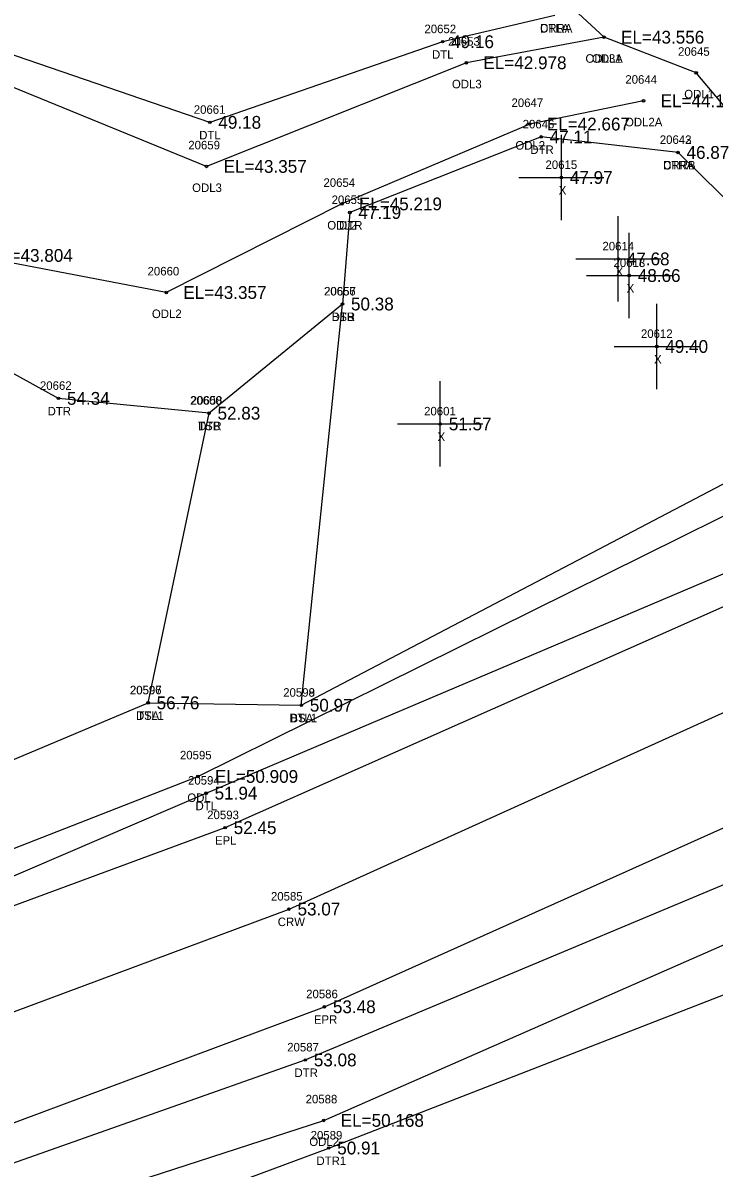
# Model space of a CAD drawing. Extents: x 2420351 to 2422725, y 845330 to 846558.
# Drawn here: x 2421635.3 to 2421716.5, y 845732.5 to 845866.8 of the extents above; entities that cross this region are included whole.
import ezdxf

# ---------------------------------------------------------------- set-up
doc = ezdxf.new("R2010")
doc.units = 0
for name, color, linetype in [('RD_DTM_BkLn1', 7, 'Continuous'), ('RD_DTM_BkLn2', 7, 'Continuous'), ('RD_DTM_BkLn_txCode', 7, 'Continuous'), ('RD_EX_H2O', 7, 'Continuous'), ('RD_EX_H2O_txCode', 7, 'Continuous'), ('RD_EX_Misc', 7, 'Continuous'), ('RD_EX_Misc_txCode', 7, 'Continuous'), ('RD_EX_Road', 7, 'Continuous'), ('RD_EX_Road_txCode', 7, 'Continuous'), ('RD_EX_TX_H2O_ELEV', 7, 'Continuous'), ('RD_EX_TX_Misc_ELEV', 7, 'Continuous'), ('RD_EX_TX_Road_ELEV', 7, 'Continuous'), ('RD_HC_Survey_ELEV', 7, 'Continuous'), ('RD_HC_Survey_txCode', 7, 'Continuous'), ('RD_SMD_Locator', 7, 'Continuous')]:
    doc.layers.add(name, color=color, linetype=linetype)

msp = doc.modelspace()

# ---------------------------------------------------------------- linework, layer by layer
at = {"layer": 'RD_DTM_BkLn1'}
msp.add_lwpolyline([(2420378.71, 845690.53), (2420439.5, 845704.09), (2420489.95, 845712.49), (2420551.89, 845719.42), (2420551.95, 845719.57), (2420607.12, 845722.67), (2420682.92, 845723.04), (2420749.65, 845719.68), (2420796.31, 845715.7), (2420900.74, 845705.33), (2421018.16, 845694.11), (2421114.61, 845684.8), (2421175.74, 845680.1), (2421234.97, 845678.35), (2421292.42, 845679.46), (2421350.56, 845683.65), (2421414.53, 845692.12), (2421472.54, 845703.63), (2421533.08, 845718.31), (2421555.4, 845725.02), (2421609.81, 845741.71), (2421666.58, 845762.88), (2421744.67, 845798.22)], dxfattribs=at)
at = {"layer": 'RD_DTM_BkLn2'}
for p, q in [((2421668.02, 845786.79), (2421672.85, 845833.86)), ((2421650.04, 845787.07), (2421657.19, 845821.05))]:
    msp.add_line(p, q, dxfattribs=at)
at = {"layer": 'RD_EX_H2O'}
for points in [[(2420975.55, 846190.58), (2420976.37, 846105.11), (2420974.31, 845997.82), (2420976.03, 845896.74), (2420974.59, 845794.18), (2420975.37, 845743.63), (2420984.12, 845720.99), (2420999.91, 845711.18), (2421116.7, 845699.77), (2421177.35, 845696.01), (2421236.57, 845694.11), (2421292.07, 845694.75), (2421349.67, 845700.43), (2421411.57, 845706.56), (2421470.63, 845718.76), (2421529.96, 845732.93), (2421551.14, 845737.51), (2421602.97, 845753.33), (2421656.85, 845776.48), (2421724.45, 845805.15), (2421739.21, 845812.56)], [(2420980.17, 846190.47), (2420980.93, 846104.85), (2420980.02, 845997.99), (2420979.17, 845896.92), (2420978.72, 845794), (2420978.72, 845743.89), (2420987.58, 845724.3), (2421000.53, 845717.13), (2421117.24, 845704.33), (2421178.3, 845699.94), (2421237.1, 845697.97), (2421292.37, 845698.66), (2421349.43, 845702.84), (2421410.88, 845710.25), (2421469.94, 845721.7), (2421529.19, 845736.54), (2421550.26, 845742.27), (2421602, 845757.38), (2421655.89, 845778.44), (2421721.41, 845810.89), (2421742.22, 845823.45)], [(2421769.97, 845784.59), (2421757.53, 845787.6), (2421742.96, 845811.73), (2421745.62, 845824.92), (2421731.55, 845840.59), (2421714.37, 845860.98), (2421703.55, 845865.16), (2421670.27, 845895.91), (2421653.18, 845938.84), (2421661.84, 845966.62), (2421645.65, 846012.9), (2421638.29, 846027.24), (2421576.72, 846012.28), (2421545.4, 846011.31), (2421531.8, 846021.91), (2421540.87, 846056.88), (2421568.83, 846092.43), (2421605.18, 846118.43)], [(2421712.23, 845851.64), (2421696.17, 845853.46), (2421673.72, 845844.59), (2421672.85, 845833.86), (2421657.19, 845821.05), (2421639.52, 845822.79), (2421628.75, 845828.72), (2421620.88, 845834.5), (2421598.01, 845848.76), (2421559.66, 845849.82), (2421519.66, 845839.33), (2421490.26, 845831.77), (2421489.16, 845834.56), (2421488.34, 845838.76), (2421481.47, 845840.1), (2421478.52, 845840.67), (2421462.88, 845836.78), (2421401.68, 845880.53), (2421390.37, 845914.71), (2421413.41, 845969.29), (2421455.53, 845995.93), (2421500.71, 846029.14), (2421506.65, 846045.11), (2421509.82, 846047.43)], [(2421708.19, 845857.7), (2421694.83, 845854.97), (2421672.77, 845845.6), (2421652.18, 845835.21), (2421629.45, 845839.56), (2421596.22, 845851.19), (2421557.52, 845853.76), (2421517.9, 845849.31), (2421470, 845855.59), (2421412.32, 845890.59), (2421407.69, 845919.26), (2421422.64, 845967.89), (2421458.88, 845993.64), (2421465.81, 845995.46), (2421507.94, 846023.27)], [(2421697.78, 845867.71), (2421684.61, 845864.63), (2421657.29, 845855.17), (2421611.89, 845870.76), (2421583.33, 845881.87), (2421549.84, 845871.2), (2421517.26, 845862.24), (2421475.01, 845867.75), (2421422.24, 845899.02), (2421422.38, 845924.44), (2421434.43, 845964.2), (2421465.61, 845987.89), (2421488.91, 845998.31), (2421509.34, 846009.28), (2421510.99, 846011.42)], [(2421703.55, 845865.16), (2421687.39, 845862.16), (2421656.9, 845850), (2421608.8, 845869.71), (2421583.67, 845874.15), (2421552.59, 845864.58), (2421517.75, 845855.15), (2421472.19, 845860.37), (2421417.44, 845896.22), (2421415.01, 845921.35), (2421431.52, 845967.08), (2421463.61, 845990.26), (2421465.81, 845995.46)], [(2421739.21, 845808.11), (2421739.21, 845812.56), (2421742.22, 845823.45), (2421740.13, 845828.42), (2421727.39, 845836.73), (2421712.23, 845851.64)], [(2421348.44, 845711.4), (2421408.11, 845718.43), (2421468.58, 845729.77), (2421526.52, 845745.24), (2421541.81, 845745.64), (2421549.75, 845745.7), (2421570.45, 845751.87), (2421591.88, 845757.66), (2421599.3, 845765.73), (2421650.04, 845787.07), (2421668.02, 845786.79), (2421719.15, 845813.59), (2421740.13, 845828.42)], [(2421462.85, 845683.51), (2421560.11, 845709.79), (2421615.97, 845726.65), (2421668.49, 845745.18), (2421738.54, 845774.52), (2421754.61, 845783.24)], [(2421462.85, 845683.51), (2421463.34, 845677.36), (2421472.12, 845675.5), (2421563.69, 845698.26), (2421619.71, 845715.72), (2421671.24, 845734.85), (2421744.95, 845763.45), (2421768.08, 845778.29)], [(2421465.82, 845681.42), (2421562.1, 845703.19), (2421618.04, 845721.04), (2421670.65, 845738.09), (2421741.88, 845769.36), (2421759.06, 845777.16)]]:
    msp.add_lwpolyline(points, dxfattribs=at)
at = {"layer": 'RD_EX_Misc'}
for p, q in [((2421698.54, 845843.7), (2421698.54, 845853.7)), ((2421693.54, 845848.7), (2421703.54, 845848.7)), ((2421705.22, 845834.15), (2421705.22, 845844.15)), ((2421706.51, 845832.2), (2421706.51, 845842.2)), ((2421700.22, 845839.15), (2421710.22, 845839.15)), ((2421701.51, 845837.2), (2421711.51, 845837.2)), ((2421709.74, 845823.88), (2421709.74, 845833.88)), ((2421704.74, 845828.88), (2421714.74, 845828.88)), ((2421684.33, 845814.79), (2421684.33, 845824.79)), ((2421679.33, 845819.79), (2421689.33, 845819.79))]:
    msp.add_line(p, q, dxfattribs=at)
at = {"layer": 'RD_EX_Road'}
for points in [[(2420388.28, 845680.39), (2420441.29, 845692.04), (2420492.62, 845700.7), (2420553.92, 845707.41), (2420607.69, 845710.85), (2420682.38, 845711.26), (2420749.44, 845707.27), (2420795.12, 845703.44), (2420900.28, 845693.42), (2421017.17, 845682.19), (2421113.9, 845672.97), (2421174.87, 845668.16), (2421234.59, 845666.13), (2421293, 845667.25), (2421351.24, 845671.5), (2421419.82, 845681.17), (2421463.19, 845688.63), (2421558.82, 845713.18), (2421614.57, 845730.45), (2421670.73, 845751.42), (2421735.61, 845780.5), (2421750.75, 845787.87), (2421744.67, 845798.22), (2421739.21, 845808.11)], [(2421350.22, 845695.49), (2421412.35, 845704.28), (2421471.12, 845715.7), (2421530.23, 845730.14), (2421551.47, 845736), (2421603.47, 845751.93), (2421659.09, 845772.43), (2421726.04, 845802.13), (2421739.21, 845808.11)]]:
    msp.add_lwpolyline(points, dxfattribs=at)
at = {"layer": 'RD_SMD_Locator'}
for centre in [(2421703.55, 845865.16), (2421703.55, 845865.16), (2421684.61, 845864.63), (2421687.39, 845862.16), (2421714.37, 845860.98), (2421708.19, 845857.7), (2421657.29, 845855.17), (2421694.83, 845854.97), (2421696.17, 845853.46), (2421712.23, 845851.64), (2421712.23, 845851.64), (2421656.9, 845850), (2421698.54, 845848.7), (2421672.77, 845845.6), (2421673.72, 845844.59), (2421705.22, 845839.15), (2421706.51, 845837.2), (2421652.18, 845835.21), (2421672.85, 845833.86), (2421672.85, 845833.86), (2421709.74, 845828.88), (2421639.52, 845822.79), (2421657.19, 845821.05), (2421657.19, 845821.05), (2421684.33, 845819.79), (2421650.04, 845787.07), (2421650.04, 845787.07), (2421668.02, 845786.79), (2421668.02, 845786.79), (2421655.89, 845778.44), (2421656.85, 845776.48), (2421659.09, 845772.43), (2421666.58, 845762.88), (2421670.73, 845751.42), (2421668.49, 845745.18), (2421670.65, 845738.09), (2421671.24, 845734.85)]:
    msp.add_circle(centre, 0.15, dxfattribs=at)

# ---------------------------------------------------------------- texts
at = {"layer": 'RD_DTM_BkLn_txCode'}
for s, p in [('20656', (2421670.68, 845834.86)), ('BSB', (2421671.6, 845831.86)), ('20600', (2421654.97, 845822.05)), ('TSB', (2421655.92, 845819.05)), ('20597', (2421647.92, 845788.07)), ('20599', (2421665.9, 845787.79)), ('TSA', (2421648.76, 845785.07)), ('BSA', (2421666.75, 845784.79))]:
    msp.add_text(s, height=1, dxfattribs=at).set_placement(p)
at = {"layer": 'RD_EX_H2O_txCode'}
for s, p in [('20652', (2421682.47, 845865.63)), ('CRRA', (2421696.04, 845865.71)), ('DTLA', (2421696.05, 845865.71)), ('20653', (2421685.25, 845864.16)), ('DTL', (2421683.36, 845862.63)), ('20645', (2421712.23, 845862.98)), ('ODL3A', (2421701.37, 845862.16)), ('ODL1', (2421702.14, 845862.16)), ('ODL3', (2421685.7, 845859.16)), ('20644', (2421706.05, 845859.7)), ('ODL1', (2421712.96, 845857.98)), ('20661', (2421655.4, 845856.17)), ('20647', (2421692.69, 845856.97)), ('20646', (2421694, 845854.46)), ('ODL2A', (2421706.01, 845854.7)), ('DTL', (2421656.04, 845853.17)), ('20659', (2421654.76, 845852)), ('ODL2', (2421693.14, 845851.97)), ('20642', (2421710.09, 845852.64)), ('20643', (2421710.09, 845852.64)), ('DTR', (2421694.9, 845851.46)), ('CRRB', (2421710.5, 845849.64)), ('DTRA', (2421710.47, 845849.64)), ('ODL3', (2421655.21, 845847)), ('20654', (2421670.62, 845847.6)), ('20655', (2421671.58, 845845.59)), ('ODL2', (2421671.07, 845842.6)), ('DTR', (2421672.45, 845842.59)), ('20660', (2421649.98, 845837.21)), ('20657', (2421670.71, 845834.86)), ('ODL2', (2421650.49, 845832.21)), ('DTR', (2421671.58, 845831.86)), ('20662', (2421637.35, 845823.79)), ('20658', (2421655.04, 845822.05)), ('DTR', (2421638.25, 845820.79)), ('DTR', (2421655.92, 845819.05)), ('20596', (2421647.9, 845788.07)), ('20598', (2421665.9, 845787.79)), ('DTL1', (2421648.63, 845785.07)), ('DTL1', (2421666.61, 845784.79)), ('20595', (2421653.78, 845780.44)), ('20594', (2421654.73, 845777.48)), ('ODL', (2421654.65, 845775.44)), ('DTL', (2421655.61, 845774.48)), ('20587', (2421666.37, 845746.18)), ('DTR', (2421667.22, 845743.18)), ('20588', (2421668.53, 845740.09)), ('ODL2', (2421668.96, 845735.09)), ('20589', (2421669.12, 845735.85)), ('DTR1', (2421669.8, 845732.85))]:
    msp.add_text(s, height=1, dxfattribs=at).set_placement(p)
at = {"layer": 'RD_EX_Misc_txCode'}
for s, p in [('20615', (2421696.68, 845849.7)), ('X', (2421698.23, 845846.7)), ('20614', (2421703.36, 845840.15)), ('20613', (2421704.66, 845838.2)), ('X', (2421704.9, 845837.15)), ('X', (2421706.2, 845835.2)), ('20612', (2421707.88, 845829.88)), ('X', (2421709.42, 845826.88)), ('20601', (2421682.43, 845820.79)), ('X', (2421684.01, 845817.79))]:
    msp.add_text(s, height=1, dxfattribs=at).set_placement(p)
at = {"layer": 'RD_EX_Road_txCode'}
for s, p in [('20593', (2421656.98, 845773.43)), ('EPL', (2421657.89, 845770.43)), ('20586', (2421668.59, 845752.42)), ('EPR', (2421669.5, 845749.42))]:
    msp.add_text(s, height=1, dxfattribs=at).set_placement(p)
at = {"layer": 'RD_EX_TX_H2O_ELEV'}
for s, p in [('49.16', (2421685.61, 845863.88)), ('EL=43.556', (2421705.55, 845864.41)), ('EL=43.556', (2421705.55, 845864.41)), ('EL=42.978', (2421689.39, 845861.41)), ('EL=44.102', (2421710.19, 845856.95)), ('49.18', (2421658.29, 845854.42)), ('EL=42.667', (2421696.83, 845854.22)), ('47.11', (2421697.17, 845852.71)), ('46.87', (2421713.23, 845850.89)), ('46.87', (2421713.23, 845850.89)), ('EL=43.357', (2421658.9, 845849.25)), ('EL=45.219', (2421674.77, 845844.85)), ('47.19', (2421674.72, 845843.84)), ('EL=43.804', (2421631.45, 845838.81)), ('EL=43.357', (2421654.18, 845834.46)), ('50.38', (2421673.85, 845833.11)), ('54.34', (2421640.52, 845822.04)), ('52.83', (2421658.19, 845820.3)), ('56.76', (2421651.04, 845786.32)), ('50.97', (2421669.02, 845786.04)), ('EL=50.909', (2421657.89, 845777.69)), ('51.94', (2421657.85, 845775.73)), ('53.08', (2421669.49, 845744.43)), ('EL=50.168', (2421672.65, 845737.34)), ('50.91', (2421672.24, 845734.1))]:
    msp.add_text(s, height=1.5, dxfattribs=at).set_placement(p)
at = {"layer": 'RD_EX_TX_Misc_ELEV'}
for s, p in [('47.97', (2421699.54, 845847.95)), ('47.68', (2421706.22, 845838.4)), ('48.66', (2421707.51, 845836.45)), ('50.38', (2421673.85, 845833.11)), ('49.40', (2421710.74, 845828.13)), ('52.83', (2421658.19, 845820.3)), ('51.57', (2421685.33, 845819.04)), ('56.76', (2421651.04, 845786.32)), ('50.97', (2421669.02, 845786.04))]:
    msp.add_text(s, height=1.5, dxfattribs=at).set_placement(p)
at = {"layer": 'RD_EX_TX_Road_ELEV'}
for s, p in [('52.45', (2421660.09, 845771.68)), ('53.48', (2421671.73, 845750.67))]:
    msp.add_text(s, height=1.5, dxfattribs=at).set_placement(p)
at = {"layer": 'RD_HC_Survey_ELEV'}
msp.add_text('53.07', height=1.5, dxfattribs=at).set_placement((2421667.58, 845762.13))
at = {"layer": 'RD_HC_Survey_txCode'}
for s, p in [('20585', (2421664.46, 845763.88)), ('CRW', (2421665.26, 845760.88))]:
    msp.add_text(s, height=1, dxfattribs=at).set_placement(p)

doc.saveas('drawing.dxf')
